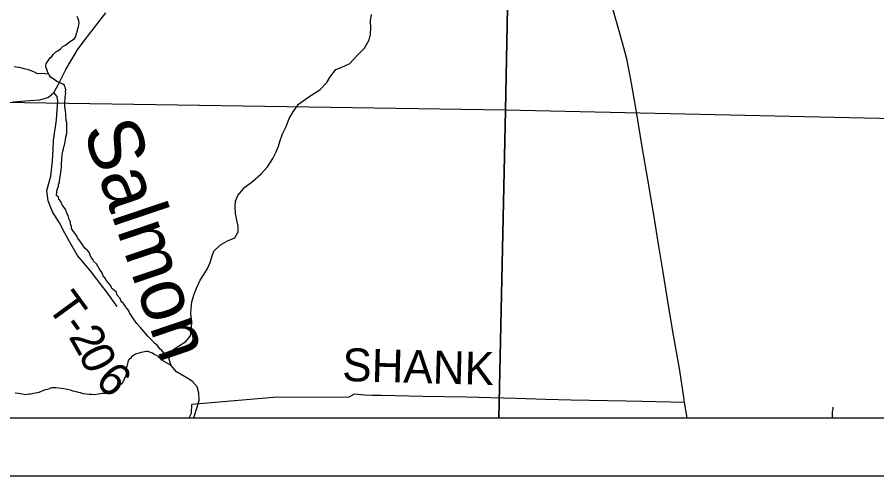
# Model space of a CAD drawing. Extents: x 0 to 34, y 0 to 22.
# Drawn here: x 6.13 to 7.614, y 14 to 14.792 of the extents above; entities that cross this region are included whole.
import ezdxf

# ---------------------------------------------------------------- set-up
doc = ezdxf.new("R2010")
doc.units = 0
for name, color, linetype in [('Default', 7, 'Continuous'), ('GM_X_County_Road', 7, 'Continuous'), ('GM_X_Minor_River', 7, 'Continuous'), ('GM_X_Minor_River_Text', 7, 'Continuous'), ('GM_X_Section', 7, 'Continuous'), ('GM_X_Township_Road', 7, 'Continuous'), ('GM_X_Township_Road_Text', 7, 'Continuous'), ('GM_X_US_Route', 7, 'Continuous'), ('SH_Data', 7, 'Continuous')]:
    doc.layers.add(name, color=color, linetype=linetype)

msp = doc.modelspace()

# ---------------------------------------------------------------- linework, layer by layer
at = {"layer": 'Default'}
for points in [[(5.898, 14.1), (8.9, 14.1), (8.9, 17.6104), (8.0065, 17.6245), (7.0308, 17.6406), (6.9889, 17.643), (5.9893, 17.6676), (5.9888, 17.6433), (5.9796, 17.2537), (5.9756, 17.0812), (5.9658, 16.6637), (5.9579, 16.0817), (5.9546, 15.9939), (5.9496, 15.8622), (5.9475, 15.8049), (5.945, 15.7379), (5.9423, 15.6675), (5.9419, 15.65), (5.9251, 14.9951), (5.9162, 14.6505)], [(5.8991, 14.1), (6.9613, 14.1), (6.9732, 14.6315), (5.9159, 14.648)], [(6.9613, 14.1), (7.9469, 14.1), (7.9542, 14.61), (6.9732, 14.6315)]]:
    msp.add_lwpolyline(points, close=True, dxfattribs=at)
at = {"layer": 'GM_X_County_Road'}
msp.add_lwpolyline([(6.1228, 14.6461), (6.1527, 14.6486), (6.1696, 14.6497), (6.1792, 14.6522), (6.1842, 14.6543), (6.1936, 14.6621), (6.2005, 14.6741), (6.2145, 14.7017), (6.2346, 14.7362), (6.2458, 14.7517), (6.2653, 14.7771), (6.2832, 14.7997)], dxfattribs=at)
at = {"layer": 'GM_X_Minor_River'}
for points in [[(6.2143, 14.6255), (6.214, 14.63), (6.2133, 14.6342), (6.2127, 14.6381), (6.2127, 14.6407), (6.2125, 14.6464), (6.213, 14.6521), (6.2134, 14.6548), (6.2135, 14.6582), (6.2143, 14.6604), (6.214, 14.6642), (6.2141, 14.6669), (6.2138, 14.67), (6.2127, 14.6723), (6.212, 14.6749), (6.2094, 14.6769), (6.2056, 14.6785), (6.203, 14.6797), (6.2007, 14.6809), (6.1985, 14.6821), (6.1943, 14.6845), (6.188, 14.6888), (6.1861, 14.6915), (6.185, 14.6942), (6.1832, 14.6966), (6.1829, 14.6988), (6.1807, 14.7038), (6.1796, 14.7062), (6.1797, 14.7084), (6.1805, 14.7118), (6.1821, 14.7148), (6.1856, 14.7201), (6.188, 14.723), (6.1903, 14.7245), (6.1927, 14.7279), (6.1973, 14.7323), (6.2008, 14.7341), (6.2054, 14.7378), (6.209, 14.7419), (6.2136, 14.7441), (6.2198, 14.7492), (6.2221, 14.7507), (6.2255, 14.7525), (6.2294, 14.7555), (6.2318, 14.7592), (6.233, 14.7641), (6.2343, 14.7687), (6.2347, 14.7709), (6.2364, 14.7758), (6.2368, 14.7789), (6.2372, 14.7815), (6.2366, 14.7861), (6.2355, 14.7895), (6.2337, 14.7938)], [(6.4354, 14.1), (6.4365, 14.1039), (6.4405, 14.1167), (6.4442, 14.1303), (6.444, 14.1429), (6.4408, 14.1536), (6.4326, 14.1636), (6.4191, 14.1718), (6.4052, 14.1797), (6.3963, 14.1905), (6.392, 14.2031), (6.3972, 14.2163), (6.4106, 14.2252), (6.4214, 14.2318), (6.4295, 14.242), (6.4313, 14.2545), (6.4315, 14.267), (6.4302, 14.2792), (6.4304, 14.2894), (6.4317, 14.3008), (6.4357, 14.3137), (6.4401, 14.3239), (6.4464, 14.3378), (6.4523, 14.3476), (6.4589, 14.3581), (6.4633, 14.3683), (6.4661, 14.3785), (6.4697, 14.3883), (6.4813, 14.3991), (6.4936, 14.4058), (6.5062, 14.4109), (6.5117, 14.4218), (6.5115, 14.4313), (6.5094, 14.4416), (6.5073, 14.453), (6.5064, 14.4648), (6.5074, 14.4743), (6.511, 14.4845), (6.5234, 14.4987), (6.5364, 14.5084), (6.5507, 14.5211), (6.5623, 14.5338), (6.5717, 14.5484), (6.5772, 14.5597), (6.5812, 14.5695), (6.5844, 14.5794), (6.5884, 14.5907), (6.5943, 14.6035), (6.5995, 14.6171), (6.6069, 14.6291), (6.6159, 14.6423), (6.6317, 14.6538), (6.642, 14.6601), (6.6524, 14.6671), (6.6648, 14.6798), (6.6707, 14.6896), (6.68, 14.702), (6.6895, 14.7056), (6.7045, 14.7126), (6.7168, 14.7256), (6.73, 14.7391), (6.7378, 14.753), (6.7403, 14.7632), (6.7409, 14.7739), (6.7403, 14.786), (6.7421, 14.797)], [(6.185, 14.6942), (6.1717, 14.6949), (6.1657, 14.6947), (6.1604, 14.6971), (6.1544, 14.6999), (6.1498, 14.7012), (6.1427, 14.7033), (6.1366, 14.7049), (6.1324, 14.7054), (6.1252, 14.7067)], [(6.392, 14.2031), (6.3839, 14.2119), (6.3798, 14.2166), (6.3772, 14.2186), (6.3746, 14.2217), (6.3728, 14.2251), (6.3675, 14.229), (6.3623, 14.2349), (6.356, 14.2415), (6.3494, 14.2489), (6.3427, 14.2567), (6.3368, 14.2633), (6.332, 14.2695), (6.3301, 14.2729), (6.3272, 14.2776), (6.3246, 14.2803), (6.3243, 14.2826), (6.3213, 14.2872), (6.3184, 14.2899), (6.3177, 14.2922), (6.314, 14.2976), (6.311, 14.3), (6.3095, 14.3027), (6.3081, 14.3062), (6.3029, 14.312), (6.3011, 14.3177), (6.2937, 14.3236), (6.2922, 14.3282), (6.2863, 14.3352), (6.2845, 14.3375), (6.2815, 14.3418), (6.2789, 14.3441), (6.2786, 14.3464), (6.2753, 14.353), (6.2727, 14.3572), (6.2673, 14.3665), (6.262, 14.3708), (6.2613, 14.3734), (6.258, 14.3773), (6.2566, 14.3812), (6.2551, 14.3854), (6.2522, 14.3889), (6.2477, 14.3928), (6.2433, 14.399), (6.2411, 14.4017), (6.2367, 14.4083), (6.2344, 14.411), (6.2337, 14.4133), (6.2308, 14.4175), (6.2264, 14.4237), (6.2242, 14.4272), (6.2239, 14.431), (6.2224, 14.4352), (6.2221, 14.439), (6.22, 14.4429), (6.2186, 14.4498), (6.2164, 14.4525), (6.215, 14.4575), (6.2143, 14.4598), (6.2117, 14.4636), (6.208, 14.4683), (6.2069, 14.4706), (6.2062, 14.4733), (6.2025, 14.4779), (6.2014, 14.4814), (6.1981, 14.4841), (6.1986, 14.4905), (6.1991, 14.4947), (6.2015, 14.5004), (6.2016, 14.5038), (6.2032, 14.5064), (6.2036, 14.5094), (6.2041, 14.5132), (6.2054, 14.5208), (6.2059, 14.5242), (6.2064, 14.5299), (6.2068, 14.5325), (6.207, 14.5409), (6.2075, 14.5447), (6.2076, 14.5485), (6.2081, 14.5542), (6.2094, 14.561), (6.2102, 14.5648), (6.2107, 14.5682), (6.2119, 14.5712), (6.2136, 14.5806), (6.2145, 14.5848), (6.2158, 14.5912), (6.2159, 14.5954), (6.2163, 14.6003), (6.2161, 14.6045), (6.2161, 14.6068), (6.2158, 14.6102), (6.2151, 14.614), (6.2148, 14.6175), (6.2141, 14.6205), (6.2143, 14.6255)], [(6.3963, 14.1905), (6.3809, 14.1991), (6.3753, 14.2042), (6.3735, 14.2069), (6.3682, 14.2089), (6.3641, 14.2117), (6.3607, 14.2133), (6.3566, 14.2145), (6.3531, 14.2146), (6.3443, 14.2129), (6.3386, 14.2115), (6.3348, 14.2101), (6.3309, 14.2079), (6.3278, 14.2057), (6.3259, 14.2027), (6.3235, 14.2013), (6.322, 14.199), (6.3215, 14.1964), (6.3199, 14.1918), (6.319, 14.1877), (6.3193, 14.1812), (6.3192, 14.1786), (6.3183, 14.1733), (6.3152, 14.168), (6.3144, 14.1654), (6.3108, 14.159), (6.3077, 14.1564), (6.3057, 14.1542), (6.3018, 14.1486), (6.2991, 14.1471), (6.2949, 14.145), (6.2922, 14.1443), (6.2845, 14.1422), (6.2777, 14.142), (6.2708, 14.141), (6.2632, 14.14), (6.2586, 14.1402), (6.2545, 14.1406), (6.2499, 14.1408), (6.2446, 14.1416), (6.2397, 14.1433), (6.2363, 14.1441), (6.2302, 14.1454), (6.2264, 14.1463), (6.2242, 14.1471), (6.2174, 14.1492), (6.2109, 14.1501), (6.2068, 14.1509), (6.1969, 14.1519), (6.1904, 14.1517), (6.1878, 14.1514), (6.1855, 14.1503), (6.1824, 14.1493), (6.1793, 14.1486), (6.1759, 14.1475), (6.1678, 14.1439), (6.1621, 14.1429), (6.1587, 14.1422), (6.1541, 14.1412), (6.1518, 14.1409), (6.1483, 14.1402), (6.1453, 14.1399), (6.1423, 14.1404), (6.1389, 14.1408), (6.1358, 14.1417), (6.1324, 14.1421), (6.1271, 14.143)], [(7.5382, 14.1), (7.5375, 14.1016), (7.5372, 14.1046), (7.5372, 14.1073), (7.5377, 14.1103), (7.5381, 14.1126), (7.5386, 14.1156), (7.5386, 14.1183)]]:
    msp.add_lwpolyline(points, dxfattribs=at)
at = {"layer": 'GM_X_Section'}
for points in [[(6.9929, 15.633), (6.9732, 14.6315), (5.9159, 14.648), (5.9463, 15.655)], [(7.9729, 15.6119), (7.9542, 14.61), (6.9732, 14.6315), (6.9929, 15.633)]]:
    msp.add_lwpolyline(points, close=True, dxfattribs=at)
at = {"layer": 'GM_X_Township_Road'}
for points in [[(6.1923, 14.5639), (6.193, 14.5794), (6.198, 14.6153), (6.1994, 14.6322), (6.2004, 14.647), (6.1995, 14.6552), (6.1936, 14.6621)], [(6.2128, 14.4193), (6.2033, 14.4368), (6.1914, 14.4559), (6.1838, 14.4752), (6.1814, 14.4928), (6.1884, 14.5176), (6.1914, 14.5439), (6.1923, 14.5639)], [(6.3029, 14.2926), (6.2852, 14.3173), (6.2562, 14.3545), (6.2347, 14.3808), (6.2215, 14.4034), (6.2128, 14.4193)], [(6.7426, 14.1389), (6.7306, 14.1392), (6.7121, 14.1408), (6.7028, 14.1358), (6.5726, 14.1351), (6.4319, 14.123)], [(7.2821, 14.1264), (7.2088, 14.1283), (7.1807, 14.1291), (7.0866, 14.1308), (7.0423, 14.1318), (6.9917, 14.1333), (6.9045, 14.1361), (6.8306, 14.1372), (6.7584, 14.1386), (6.7426, 14.1389)], [(6.4271, 14.1), (6.4312, 14.1084), (6.4319, 14.123)]]:
    msp.add_lwpolyline(points, dxfattribs=at)
at = {"layer": 'GM_X_US_Route'}
msp.add_lwpolyline([(7.2868, 14.1), (7.2821, 14.1264), (7.2808, 14.1361), (7.2733, 14.1853), (7.2617, 14.2496), (7.2521, 14.3088), (7.2452, 14.3516), (7.2376, 14.3966), (7.2289, 14.4511), (7.2185, 14.5118), (7.2091, 14.5683), (7.1996, 14.6255), (7.1905, 14.6781), (7.1823, 14.7205), (7.1774, 14.7396), (7.1707, 14.7625), (7.1584, 14.8069)], dxfattribs=at)
at = {"layer": 'SH_Data'}
for p, q in [((2.1, 14.1), (8.9, 14.1)), ((2, 14), (9, 14))]:
    msp.add_line(p, q, dxfattribs=at)

# ---------------------------------------------------------------- texts
at = {"layer": 'GM_X_Minor_River_Text'}
msp.add_text('Salmon', height=0.09473, rotation=288.6739, dxfattribs=at).set_placement((6.2432, 14.5981))
at = {"layer": 'GM_X_Township_Road_Text'}
for s, height, rotation, p in [('T', 0.0568, 306.1696, (6.1806, 14.2923)), ('2', 0.0568, 299.5162, (6.2183, 14.2405)), ('-', 0.0568, 305.5334, (6.2056, 14.2581)), ('0', 0.0568, 295.4572, (6.2351, 14.2109)), ('SHANK', 0.05682, 358.4266, (6.6908, 14.1639)), ('6', 0.0568, 315.556, (6.2627, 14.1617))]:
    msp.add_text(s, height=height, rotation=rotation, dxfattribs=at).set_placement(p)

doc.saveas('drawing.dxf')
